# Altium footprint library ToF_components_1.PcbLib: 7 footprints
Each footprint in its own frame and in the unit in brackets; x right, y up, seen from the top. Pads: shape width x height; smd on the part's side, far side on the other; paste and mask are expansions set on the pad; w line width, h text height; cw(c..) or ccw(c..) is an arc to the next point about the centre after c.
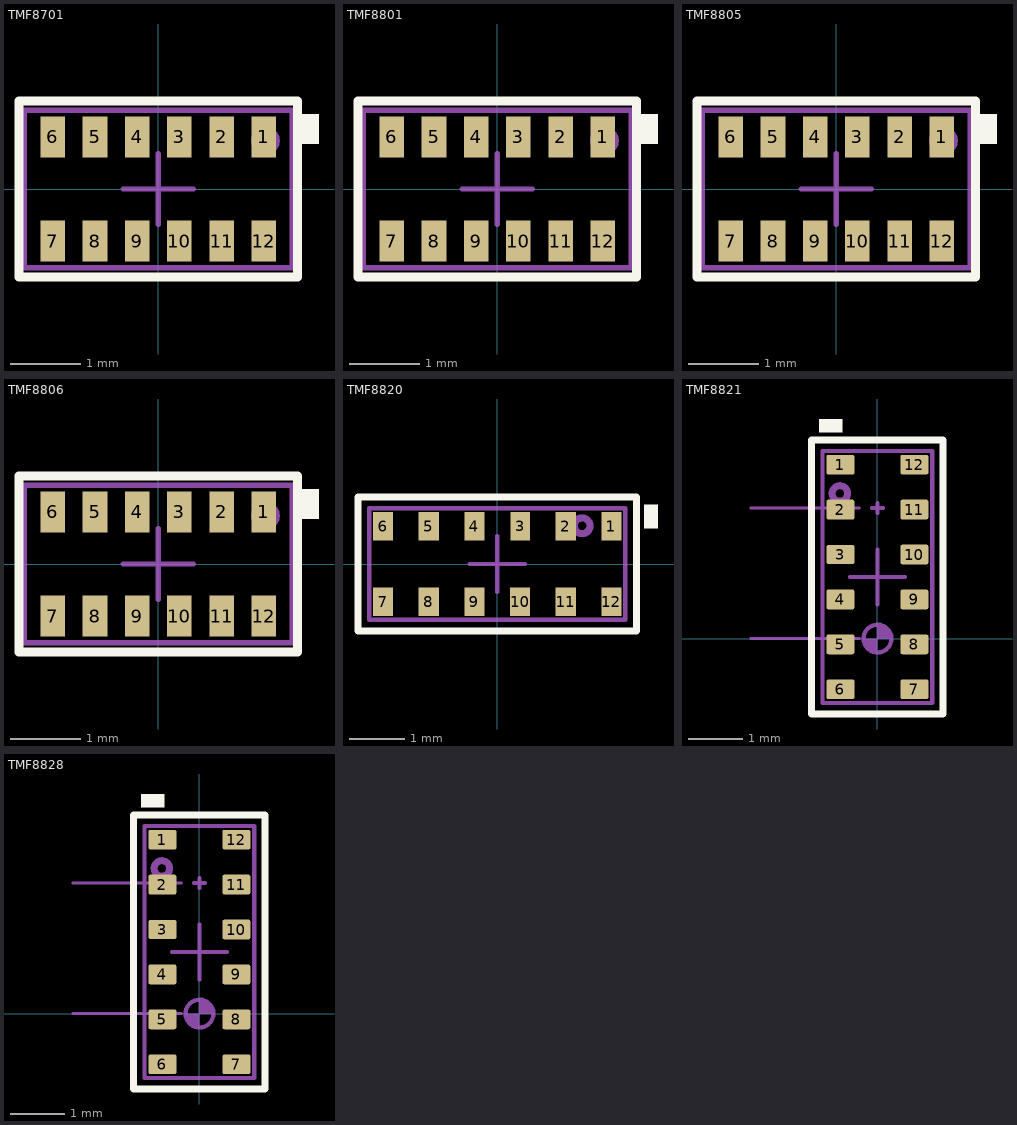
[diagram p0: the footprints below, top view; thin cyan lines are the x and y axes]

## TMF8701 [mm] "TMF8701"
height 0.74
pads (12):
  rect 0.35x0.58 smd mask+0.075: 1(1.5,0.74) 2(0.9,0.74) 3(0.3,0.74) 4(-0.3,0.74) 5(-0.9,0.74) 6(-1.5,0.74) 7(-1.5,-0.74) 8(-0.9,-0.74) 9(-0.3,-0.74) 10(0.3,-0.74) 11(0.9,-0.74) 12(1.5,-0.74)
Top Overlay:
  rectangle: 2.036,0.642 2.286,1.067
  lines w0.127: -1.981,-1.25 -1.981,1.25 1.981,1.25 1.981,-1.25 -1.981,-1.25
Mechanical 1:
  lines w0.075: -0.5,0 0.5,0 ; 0,-0.5 0,0.5
Top Assembly:
  circle w0.127: c1.524,0.686 r0.141
  lines w0.076: -1.905,-1.118 1.905,-1.118 1.905,1.118 -1.905,1.118 -1.905,-1.118
  text "'.Designator'" at -1.8,-0.2 h0.75
3D body "TMF8701_2017-12-04.STEP": height 1, standoff 0, extent -1.799,-1.1 1.803,1.1

## TMF8801 [mm] "TMF8801"
height 0.74
pads (12):
  rect 0.35x0.58 smd mask+0.075: 1(1.5,0.74) 2(0.9,0.74) 3(0.3,0.74) 4(-0.3,0.74) 5(-0.9,0.74) 6(-1.5,0.74) 7(-1.5,-0.74) 8(-0.9,-0.74) 9(-0.3,-0.74) 10(0.3,-0.74) 11(0.9,-0.74) 12(1.5,-0.74)
Top Overlay:
  rectangle: 2.036,0.642 2.286,1.067
  lines w0.127: -1.981,-1.25 -1.981,1.25 1.981,1.25 1.981,-1.25 -1.981,-1.25
Mechanical 1:
  lines w0.075: -0.5,0 0.5,0 ; 0,-0.5 0,0.5
Top Assembly:
  circle w0.127: c1.524,0.686 r0.141
  lines w0.076: -1.905,-1.118 1.905,-1.118 1.905,1.118 -1.905,1.118 -1.905,-1.118
  text "'.Designator'" at -1.8,-0.2 h0.75
3D body "TMF8701_2017-12-04.STEP": height 1, standoff 0, extent -1.799,-1.1 1.803,1.1

## TMF8805 [mm] "TMF8805"
height 0.74
pads (12):
  rect 0.35x0.58 smd mask+0.075: 1(1.5,0.74) 2(0.9,0.74) 3(0.3,0.74) 4(-0.3,0.74) 5(-0.9,0.74) 6(-1.5,0.74) 7(-1.5,-0.74) 8(-0.9,-0.74) 9(-0.3,-0.74) 10(0.3,-0.74) 11(0.9,-0.74) 12(1.5,-0.74)
Top Overlay:
  rectangle: 2.036,0.642 2.286,1.067
  lines w0.127: -1.981,-1.25 1.981,-1.25 1.981,1.25 -1.981,1.25 -1.981,-1.25
Mechanical 1:
  lines w0.075: -0.5,0 0.5,0 ; 0,-0.5 0,0.5
Top Assembly:
  circle w0.127: c1.524,0.686 r0.141
  lines w0.076: -1.905,-1.118 -1.905,1.118 1.905,1.118 1.905,-1.118 -1.905,-1.118
  text "'.Designator'" at -1.8,-0.2 h0.75
3D body "TMF8701_2017-12-04.STEP": height 1, standoff 0, extent -1.799,-1.1 1.803,1.1

## TMF8806 [mm] "TMF8806"
height 0.74
pads (12):
  rect 0.35x0.58 smd mask+0.075: 1(1.5,0.74) 2(0.9,0.74) 3(0.3,0.74) 4(-0.3,0.74) 5(-0.9,0.74) 6(-1.5,0.74) 7(-1.5,-0.74) 8(-0.9,-0.74) 9(-0.3,-0.74) 10(0.3,-0.74) 11(0.9,-0.74) 12(1.5,-0.74)
Top Overlay:
  rectangle: 2.036,0.642 2.286,1.067
  lines w0.127: -1.981,-1.25 -1.981,1.25 1.981,1.25 1.981,-1.25 -1.981,-1.25
Mechanical 1:
  lines w0.075: -0.5,0 0.5,0 ; 0,-0.5 0,0.5
Top Assembly:
  circle w0.127: c1.524,0.686 r0.141
  lines w0.076: -1.905,-1.118 1.905,-1.118 1.905,1.118 -1.905,1.118 -1.905,-1.118
  text "'.Designator'" at -1.8,-0.2 h0.75
3D body "TMF8701_2017-12-04.STEP": height 1, standoff 0, extent -1.799,-1.1 1.803,1.1

## TMF8820 [mm] "TMF8820"
height 0.74
pads (12):
  rect 0.36x0.51 smd: 1(2.05,0.675) 2(1.23,0.675) 4(-0.41,0.675) 5(-1.23,0.675) 6(-2.05,0.675) 7(-2.05,-0.675) 8(-1.23,-0.675) 9(-0.41,-0.675) 10(0.41,-0.675) 11(1.23,-0.675) 12(2.05,-0.675)
  rect 0.35x0.51 smd: 3(0.41,0.675)
Top Overlay:
  rectangle: 2.636,0.642 2.886,1.067
  lines w0.127: -2.5,-1.2 -2.5,1.2 2.5,1.2 2.5,-1.2 -2.5,-1.2
Mechanical 1:
  lines w0.075: -0.5,0 0.5,0 ; 0,-0.5 0,0.5
Top Assembly:
  circle w0.127: c1.524,0.686 r0.141
  lines w0.076: -2.3,-1 2.3,-1 2.3,1 -2.3,1 -2.3,-1
  text "'.Designator'" at -1.8,-0.2 h0.75
3D body "Bedwell_V14.STEP": height 1.2, standoff -0.2, extent -2.3,-1 2.3,1

## TMF8821 [mm]
height 0.8
pads (12):
  rrect20% 0.51x0.36 smd mask+0.05: 1(-0.675,3.175) 2(-0.675,2.355) 4(-0.675,0.715) 5(-0.675,-0.105) 6(-0.675,-0.925) 7(0.675,-0.925) 8(0.675,-0.105) 9(0.675,0.715) 10(0.675,1.535) 11(0.675,2.355) 12(0.675,3.175)
  rrect20% 0.51x0.35 smd mask+0.05: 3(-0.675,1.535)
Top Overlay:
  region: -0.642,3.761 -0.642,4.011 -1.067,4.011 -1.067,3.761
  lines w0.127: -1.2,-1.375 1.2,-1.375 1.2,3.625 -1.2,3.625 -1.2,-1.375
Mechanical 2:
  region: 0,-0.268 -0.053,-0.268 -0.152,-0.227 -0.227,-0.152 -0.268,-0.054 -0.268,0 0,0
  region: 0,0.291 0.058,0.291 0.165,0.247 0.247,0.165 0.291,0.058 0.291,0 0,0
  lines w0.051: -2.311,0.002 -0.327,0 ; -2.311,2.385 -0.327,2.383
  lines w0.076: -0.102,2.383 0.102,2.383 ; 0,2.291 0,2.469 ; 0.254,0 cw(c0,0) 0.254,0.009
  text "VCSEL" at -4.834,2.131 h0.51
  text "SPAD" at -4.326,-0.252 h0.51
Board:
  lines w0.075: -0.5,1.125 0.5,1.125 ; 0,0.625 0,1.625
Top Assembly:
  circle w0.127: c-0.686,2.649 r0.141
  lines w0.076: -1,-1.175 1,-1.175 1,3.425 -1,3.425 -1,-1.175
3D body "TMF8828_FoI_FoV_PD001050_1-00.STEP": height 1.45, standoff 0.05, extent -1,-1.175 1,3.425

## TMF8828 [mm] "Optical Sensor 0.394\" ~ 196.85\" (10mm ~ 5000mm) Push-Pull Output"
height 0.8
pads (12):
  rrect20% 0.51x0.36 smd mask+0.05: 1(-0.675,3.175) 2(-0.675,2.355) 4(-0.675,0.715) 5(-0.675,-0.105) 6(-0.675,-0.925) 7(0.675,-0.925) 8(0.675,-0.105) 9(0.675,0.715) 10(0.675,1.535) 11(0.675,2.355) 12(0.675,3.175)
  rrect20% 0.51x0.35 smd mask+0.05: 3(-0.675,1.535)
Top Overlay:
  region: -0.642,3.761 -0.642,4.011 -1.067,4.011 -1.067,3.761
  lines w0.127: -1.2,-1.375 -1.2,3.625 1.2,3.625 1.2,-1.375 -1.2,-1.375
Mechanical 2:
  region: 0,0.291 0.058,0.291 0.165,0.247 0.247,0.165 0.291,0.058 0.291,0 0,0
  region: 0,-0.268 -0.053,-0.268 -0.152,-0.227 -0.227,-0.152 -0.268,-0.054 -0.268,0 0,0
  lines w0.051: -2.311,0.002 -0.327,0 ; -2.311,2.385 -0.327,2.383
  lines w0.076: -0.102,2.383 0.102,2.383 ; 0,2.291 0,2.469 ; 0.254,0 cw(c0,0) 0.254,0.009
  text "SPAD" at -4.326,-0.252 h0.51
  text "VCSEL" at -4.834,2.131 h0.51
Board:
  lines w0.075: -0.5,1.125 0.5,1.125 ; 0,0.625 0,1.625
Top Assembly:
  circle w0.127: c-0.686,2.649 r0.141
  lines w0.076: -1,-1.175 -1,3.425 1,3.425 1,-1.175 -1,-1.175
3D body "TMF8828_FoI_FoV_PD001050_1-00.STEP": height 1.45, standoff 0.05, extent -1,-1.175 1,3.425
